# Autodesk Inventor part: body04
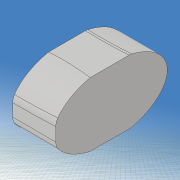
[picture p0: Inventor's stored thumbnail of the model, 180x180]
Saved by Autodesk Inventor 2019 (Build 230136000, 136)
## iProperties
Created: 2020-12
Part Number: body04
Material: 一般
Document SubType Name: Modeling
Designer: kikut
Density: 1 g/cm^3
Appearance: 既定
Mass: 87.6477 g
Surface Area: 156.124 cm^2
Volume: 87.6477 cm^3
Author: kikut
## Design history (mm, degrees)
sketch "スケッチ1"
  geometry: L1 (-100, -20)-(100, -20); L2 (100, -20)-(100, 20); L3 (100, 20)-(-100, 20); L4 (-100, 20)-(-100, -20); L5 (-100, -20)-(100, 20); L6 (100, -20)-(-100, 20); 1 further point
  constraints: 12 end point, 2 midpoint, 2 parallel, 1 horizontal, 1 perpendicular
  dimensions: "d0" = 40 distance of L3.end L1.start; "d1" = 200 distance of L2.end L3.end
extrude "押し出し1" new body sketch "スケッチ1" stored distance "d2" = 60; taper "d3" = 0 deg
sketch "スケッチ2"
  geometry: L1 (0, -60)-(0, 0) reference; L2 (200, -60)-(200, 0) reference; L3 (0, 0)-(200, 0) reference; L4 (200, -60)-(0, -60) reference; L5 (0, -26)-(0, -32); L6 (194, -10)-(194, -13); L7 (194, -13)-(174, -33); L8 (174, -33)-(200, -58); L9 (-20, 20)-(220, 20); L10 (220, 20)-(220, -100); L11 (220, -100)-(-20, -100); L12 (-20, -100)-(-20, 20); 12 further points
  constraints: 16 end point, 4 point on line, 2 parallel, 2 vertical, 1 horizontal, 1 perpendicular, 14 other
  dimensions: "d4" = 32 distance from line of point (32, -12) L1; "d5" = 50 horizontal distance of point (32, -12) point (82, -11); "d6" = 50 horizontal distance of point (132, -17) point (82, -11); "d7" = 12 distance from line of point (32, -12) L3; "d8" = 11 distance from line of point (82, -11) L3; "d10" = 17 distance from line of point (132, -17) L3; "d11" = 26 distance from line of L5.start L3; "d12" = 0 distance from line of point (200, -60) L4; "d13" = 28 distance from line of L5.end L4; "d14" = 12 distance from line of point (28, -48) L4; "d15" = 10 distance from line of point (80, -50) L4; "d16" = 16 distance from line of point (130, -44) L4; "d17" = 28 distance from line of point (28, -48) L1; "d19" = 50 horizontal distance of point (130, -44) point (80, -50); "d20" = 80 distance from line of point (80, -50) L1; "d21" = 6 distance from line of L6.start L2; "d22" = 36 distance from line of point (164, -24) L2; "d23" = 24 distance from line of point (176, -20) L2; "d24" = 10 distance from line of L6.start L3; "d25" = 20 distance from line of point (176, -20) L3; "d26" = 24 distance from line of point (164, -24) L3; "d27" = 40 distance from line of point (160, -40) L2; "d28" = 25 distance from line of point (175, -47.5) L2; "d29" = 12.5 distance from line of point (175, -47.5) L4; "d30" = 20 distance from line of L4 point (160, -40); "d31" = 3 distance of L6.start L6.end; "d32" = 33 distance from line of L7.end L3; "d33" = 26 distance from line of L7.end L2; "d34" = 2 distance of L8.end L2.start; "d35" = 120 distance of L11.end L9.start; "d36" = 240 distance of L10.end L11.end; "d37" = 20 distance between parallel lines of L1 L12; "d38" = 20 distance between parallel lines of L3 L9
extrude "押し出し2" cut sketch "スケッチ2" extent not by distance; stored distance "d39" = 0.02; taper "d40" = 0 deg
sketch "スケッチ8"
  geometry: L1 (-100, -20)-(-100, 20) reference; L2 (100, 20)-(100, -20) reference; L3 (-142.805, 0)-(142.831, 0) reference; L4 (110, 30)-(-110, 30); L5 (-110, 30)-(-110, -30); L6 (-110, -30)-(110, -30); L7 (110, -30)-(110, 30); L8 (110, 30)-(-110, -30); L9 (-110, 30)-(110, -30); L10 (-100, -2)-(-100, 2); L11 (100, -3)-(100, 3); 7 further points
  constraints: 16 end point, 4 point on line, 2 midpoint, 2 parallel, 2 perpendicular, 1 collinear, 1 horizontal, 10 other
  dimensions: "d93" = 2 vertical distance of point (0, 0) L10.end; "d94" = 2 vertical distance of L10.start point (0, 0); "d95" = 35 distance from line of point (-65, -10) L1; "d96" = 0 horizontal distance of point (-65, 10) point (-65, -10); "d97" = 10 vertical distance of point (0, 0) point (-65, -10); "d98" = 10 vertical distance of point (-65, 10) point (0, 0); "d99" = 100 distance from line of point (0, -10) L1; "d100" = 0 horizontal distance of point (0, 10) point (0, -10); "d101" = 10 distance of point (0, -10) point (0, 0); "d102" = 10 distance of point (0, 0) point (0, 10); "d103" = 160 distance from line of point (60, -4) L1; "d104" = 0 horizontal distance of point (60, 4) point (60, -4); "d105" = 4 distance from line of L3 point (60, -4); "d106" = 4 distance from line of L3 point (60, 4); "d107" = 3 distance from line of L11.start L3; "d108" = 3 distance from line of L11.end L3; "d109" = 220 distance of L5.end L6.end; "d110" = 60 distance of L4.end L5.end
extrude "押し出し6" cut sketch "スケッチ8" extent not by distance; stored distance "d111" = 10; taper "d112" = 0 deg
sketch "スケッチ9" dims "d113" = 20, "d114" = 12
  geometry: L1 (-29, -18)-(21, -18); L2 (21, -18)-(21, 22); L3 (21, 22)-(-29, 22); L4 (-29, 22)-(-29, -18); L5 (-29, -18)-(21, 22); L6 (21, -18)-(-29, 22); 2 further points; 1 other entity
  constraints: 12 end point, 2 midpoint, 2 parallel, 1 coincident, 1 horizontal, 1 perpendicular, 2 other
  dimensions: "d115" = 50 distance of L2.end L3.end; "d116" = 40 distance of L1.end L2.end
extrude "押し出し7" cut sketch "スケッチ9" distance "d117" = 150; taper "d118" = 0 deg
fillet "フィレット4" dims "d119" = 4
fillet "フィレット5" dims "d120" = 4
fillet "フィレット6" dims "d121" = 2
node "作業平面2"
sketch "スケッチ10"
  geometry: L1 (0, -41.439)-(0, 38.458) reference; L2 (141.833, 0)-(-140.631, 0) reference; L3 (82.55, 12.983)-(81.45, -4.983); A1 r 9 centre (82, 4) between (82.55, 12.983) and (81.45, -4.983); 1 further point
  constraints: 2 end point, 2 point on circle, 1 centre point
  dimensions: "d123" = 82 distance from line of L1 A1.centre; "d124" = 4 distance from line of L2 A1.centre; "d125" = 9 radius of A1; "d126" = 180 deg dimension on A1.centre L3.end L3.start; "d127" = 90 deg dimension on L3.end point (0, 0) A1.centre
revolve "回転1" sketch "スケッチ10" stored, may be unused: angle "d128" = 90 deg
mirror "ミラー1"
sketch "スケッチ11"
  geometry: L1 (40, 30)-(25, 30); L2 (25, 30)-(25, -30); L3 (25, -30)-(40, -30); L4 (40, -30)-(40, 30); L5 (0, -40.648)-(0, 34.486) reference; L6 (140.69, 0)-(-139.196, 0) reference; L7 (120, 53.792)-(-120, 53.792); L8 (-120, 53.792)-(-120, -46.208); L9 (-120, -46.208)-(120, -46.208); L10 (120, -46.208)-(120, 53.792); 1 further point
  constraints: 16 end point, 4 parallel, 2 horizontal, 2 perpendicular, 2 other
  dimensions: "d129" = 25 distance between parallel lines of L5 L2; "d130" = 15 distance of L1.start L1.end; "d131" = 60 distance of L3.end L1.start; "d132" = 100 distance of L9.end L7.start; "d133" = 240 distance of L7.start L7.end
extrude "押し出し8" cut sketch "スケッチ11" stored distance "d134" = 40; taper "d135" = 0 deg
node "ソリッド1"
other parameters: "d122" = -1
